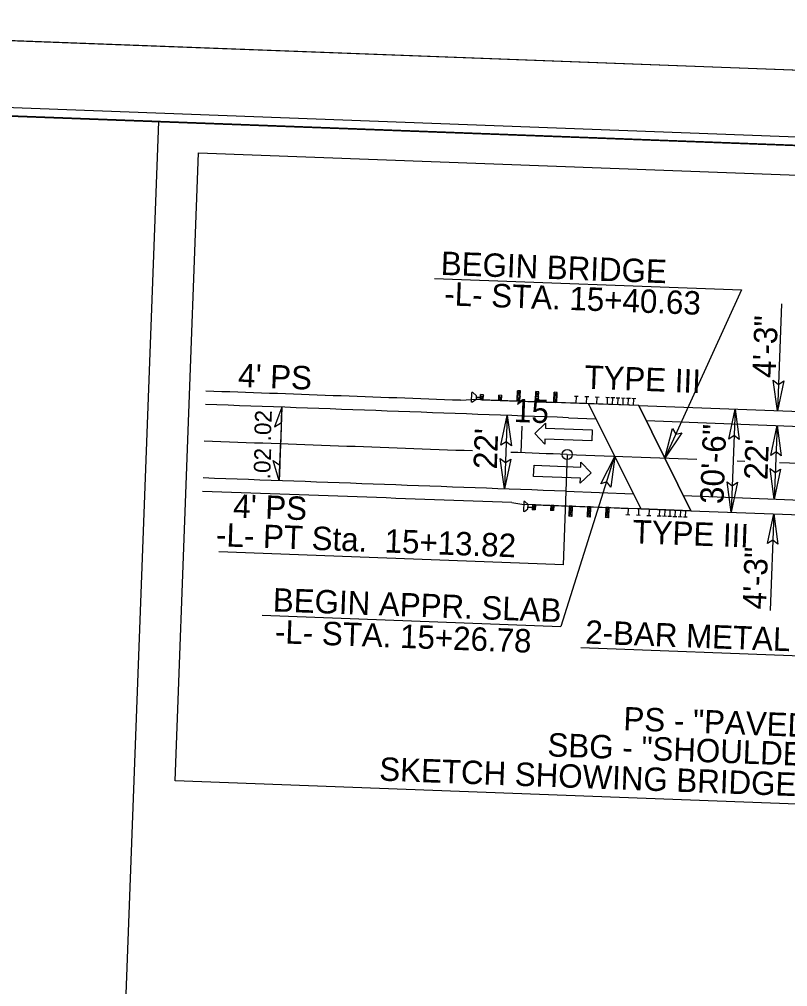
# Model space of a CAD drawing. Extents: x 2170073 to 2172001, y 723518 to 724675.
# Drawn here: x 2170287.7 to 2170517.6, y 724386.1 to 724675.4 of the extents above; entities that cross this region are included whole.
import ezdxf

# ---------------------------------------------------------------- set-up
doc = ezdxf.new("R2010")
doc.units = 0
for name, color, linetype in [('Prop Approach Slab', 7, 'Continuous'), ('Prop Approach Slab Hatching', 7, 'Continuous'), ('Prop Dimension', 7, 'Continuous'), ('Prop DSN Text', 7, 'Continuous'), ('Prop EOT', 7, 'Continuous'), ('Prop Guardrail', 7, 'Continuous'), ('Prop Guardrail Anchor Unit CELL', 7, 'Continuous'), ('Prop Horizontal Alignment', 7, 'Continuous'), ('Prop Horizontal Alignment Station Label', 7, 'Continuous'), ('Prop Horizontal Alignment Tick Label', 7, 'Continuous'), ('Prop Horizontal Alignment Tick Large', 7, 'Continuous'), ('Prop Lane Arrow CELL', 7, 'Continuous'), ('Prop Paved Shoulder', 7, 'Continuous'), ('Prop Roadway Bridge', 7, 'Continuous'), ('Prop Structure Anchor Unit CELL', 7, 'Continuous'), ('Prop Superelevation  Arrow CELL', 7, 'Continuous'), ('Prop Superelevation Label', 7, 'Continuous'), ('Prop Terminator CELL', 7, 'Continuous'), ('Sheet Clip Boundary CELL', 7, 'Continuous'), ('Sheet Cutting Line CELL', 7, 'Continuous'), ('Sheet Plan CELL', 7, 'Continuous'), ('Sheet Plan Layout CELL', 7, 'Continuous'), ('Sheet Plot Border Inside CELL', 7, 'Continuous'), ('Sheet Plot Border Outside CELL', 7, 'Continuous')]:
    doc.layers.add(name, color=color, linetype=linetype)

msp = doc.modelspace()

# ---------------------------------------------------------------- linework, layer by layer
at = {"layer": 'Prop Approach Slab'}
for p, q in [((2170473.03, 724559.86), (2170458.04, 724560.42)), ((2170458.04, 724560.42), (2170473.62, 724528.98)), ((2170488.61, 724528.42), (2170473.62, 724528.98))]:
    msp.add_line(p, q, dxfattribs=at)
at = {"layer": 'Prop Approach Slab Hatching'}
msp.add_lwpolyline([(2170473.62, 724528.98), (2170488.61, 724528.42), (2170473.03, 724559.86), (2170458.04, 724560.42)], close=True, dxfattribs=at)
at = {"layer": 'Prop Dimension'}
for p, q in [((2170411.96, 724597.89), (2170503.73, 724594.46)), ((2170503.73, 724594.46), (2170480.82, 724544.14)), ((2170515.76, 724590.29), (2170514.56, 724558.31)), ((2170433.67, 724556.91), (2170432.85, 724534.93)), ((2170501.86, 724558.78), (2170500.71, 724527.97)), ((2170514.4, 724553.89), (2170513.57, 724531.91)), ((2170465.83, 724544.7), (2170449.78, 724493.81)), ((2170513.41, 724527.5), (2170512.33, 724498.61)), ((2170360.39, 724497.16), (2170449.78, 724493.81)), ((2170455.76, 724487.5), (2170541.42, 724484.3))]:
    msp.add_line(p, q, dxfattribs=at)
at = {"layer": 'Prop DSN Text'}
msp.add_lwpolyline([(2170341.34, 724635.49), (2170729.53, 724620.96), (2170722.5, 724433.09), (2170334.32, 724447.61)], close=True, dxfattribs=at)
at = {"layer": 'Prop EOT'}
for p, q in [((2170452.07, 724556.23), (2170460.27, 724555.92)), ((2170451.25, 724534.24), (2170471.39, 724533.49))]:
    msp.add_line(p, q, dxfattribs=at)
for radius, end in [(58536.88, 87.9639731), (58514.88, 87.9639098)]:
    msp.add_arc((2168263.72, 666060.26), radius, 87.8575428, end, dxfattribs=at)
at = {"layer": 'Prop Guardrail'}
for p, q in [((2170454.29, 724560.56), (2170448.05, 724560.79)), ((2170463.63, 724529.36), (2170469.87, 724529.12))]:
    msp.add_line(p, q, dxfattribs=at)
at = {"layer": 'Prop Guardrail Anchor Unit CELL'}
for p, q in [((2170423.03, 724560.87), (2170423.15, 724563.81)), ((2170423.42, 724563.8), (2170423.15, 724563.81)), ((2170423.42, 724563.8), (2170424.41, 724562.9)), ((2170424.41, 724562.9), (2170424.37, 724561.68)), ((2170424.4, 724562.4), (2170425.69, 724562.35)), ((2170425.66, 724561.62), (2170425.72, 724563.14)), ((2170426.59, 724563.11), (2170425.66, 724561.62)), ((2170426.54, 724561.59), (2170425.71, 724563.14)), ((2170426.59, 724563.11), (2170425.72, 724563.14)), ((2170426.54, 724561.59), (2170426.59, 724563.11)), ((2170431.15, 724561.42), (2170431.2, 724562.94)), ((2170432.08, 724562.9), (2170431.15, 724561.42)), ((2170432.08, 724562.9), (2170431.2, 724562.94)), ((2170432.02, 724561.39), (2170431.2, 724562.94)), ((2170432.02, 724561.39), (2170432.08, 724562.9)), ((2170436.63, 724561.22), (2170436.75, 724564.25)), ((2170437.57, 724562.7), (2170436.63, 724561.22)), ((2170436.69, 724562.73), (2170437.62, 724564.22)), ((2170437.57, 724562.7), (2170436.69, 724562.73)), ((2170437.51, 724561.18), (2170436.69, 724562.73)), ((2170437.62, 724564.22), (2170436.75, 724564.25)), ((2170436.75, 724564.25), (2170437.57, 724562.7)), ((2170437.51, 724561.18), (2170437.62, 724564.22)), ((2170442.12, 724561.01), (2170442.23, 724564.05)), ((2170443.06, 724562.5), (2170442.12, 724561.01)), ((2170442.18, 724562.53), (2170443.11, 724564.01)), ((2170443.06, 724562.5), (2170442.18, 724562.53)), ((2170443, 724560.98), (2170442.18, 724562.53)), ((2170443.11, 724564.01), (2170442.23, 724564.05)), ((2170442.23, 724564.05), (2170443.06, 724562.5)), ((2170443, 724560.98), (2170443.11, 724564.01)), ((2170447.61, 724560.81), (2170447.72, 724563.84)), ((2170448.54, 724562.29), (2170447.61, 724560.81)), ((2170447.66, 724562.33), (2170448.6, 724563.81)), ((2170448.54, 724562.29), (2170447.66, 724562.33)), ((2170448.49, 724560.78), (2170447.66, 724562.33)), ((2170448.6, 724563.81), (2170447.72, 724563.84)), ((2170447.72, 724563.84), (2170448.54, 724562.29)), ((2170448.49, 724560.78), (2170448.6, 724563.81)), ((2170423.3, 724560.86), (2170423.03, 724560.87)), ((2170424.37, 724561.68), (2170423.3, 724560.86)), ((2170425.66, 724561.63), (2170424.37, 724561.68)), ((2170426.54, 724561.59), (2170425.66, 724561.62)), ((2170426.1, 724561.6), (2170448.05, 724560.79)), ((2170432.02, 724561.39), (2170431.15, 724561.42)), ((2170437.51, 724561.18), (2170436.63, 724561.22)), ((2170443, 724560.98), (2170442.12, 724561.01)), ((2170448.49, 724560.78), (2170447.61, 724560.81)), ((2170438.68, 724531.15), (2170438.57, 724528.21)), ((2170438.95, 724531.14), (2170438.68, 724531.15)), ((2170439.95, 724530.24), (2170438.95, 724531.14)), ((2170438.84, 724528.2), (2170438.57, 724528.21)), ((2170438.84, 724528.2), (2170439.9, 724529.02)), ((2170439.9, 724529.02), (2170439.95, 724530.24)), ((2170439.92, 724529.52), (2170441.21, 724529.48)), ((2170441.24, 724530.2), (2170439.95, 724530.24)), ((2170441.24, 724530.21), (2170441.18, 724528.69)), ((2170442.12, 724530.17), (2170441.18, 724528.69)), ((2170442.06, 724528.66), (2170441.18, 724528.69)), ((2170442.12, 724530.17), (2170441.24, 724530.21)), ((2170442.06, 724528.66), (2170441.24, 724530.21)), ((2170441.68, 724530.19), (2170463.63, 724529.36)), ((2170442.12, 724530.17), (2170442.06, 724528.66)), ((2170446.73, 724530), (2170446.67, 724528.48)), ((2170447.6, 724529.97), (2170446.67, 724528.48)), ((2170447.55, 724528.45), (2170446.67, 724528.48)), ((2170447.6, 724529.97), (2170446.73, 724530)), ((2170447.55, 724528.45), (2170446.73, 724530)), ((2170447.6, 724529.97), (2170447.55, 724528.45)), ((2170452.21, 724529.79), (2170452.1, 724526.76)), ((2170452.1, 724526.76), (2170453.03, 724528.24)), ((2170453.09, 724529.76), (2170452.15, 724528.28)), ((2170453.03, 724528.24), (2170452.15, 724528.28)), ((2170452.15, 724528.28), (2170452.98, 724526.73)), ((2170453.09, 724529.76), (2170452.21, 724529.79)), ((2170453.03, 724528.24), (2170452.21, 724529.79)), ((2170453.09, 724529.76), (2170452.98, 724526.73)), ((2170457.7, 724529.58), (2170457.59, 724526.55)), ((2170457.59, 724526.55), (2170458.52, 724528.03)), ((2170458.58, 724529.55), (2170457.64, 724528.07)), ((2170458.52, 724528.03), (2170457.64, 724528.07)), ((2170457.64, 724528.07), (2170458.46, 724526.52)), ((2170458.58, 724529.55), (2170457.7, 724529.58)), ((2170458.52, 724528.03), (2170457.7, 724529.58)), ((2170458.58, 724529.55), (2170458.46, 724526.52)), ((2170463.19, 724529.38), (2170463.07, 724526.34)), ((2170463.07, 724526.34), (2170464.01, 724527.83)), ((2170464.07, 724529.34), (2170463.13, 724527.86)), ((2170464.01, 724527.83), (2170463.13, 724527.86)), ((2170463.13, 724527.86), (2170463.95, 724526.31)), ((2170464.07, 724529.34), (2170463.19, 724529.38)), ((2170464.01, 724527.83), (2170463.19, 724529.38)), ((2170464.07, 724529.34), (2170463.95, 724526.31)), ((2170452.98, 724526.73), (2170452.1, 724526.76)), ((2170458.46, 724526.52), (2170457.59, 724526.55)), ((2170463.95, 724526.31), (2170463.07, 724526.34))]:
    msp.add_line(p, q, dxfattribs=at)
at = {"layer": 'Prop Horizontal Alignment'}
for p, q in [((2170451.66, 724545.23), (2170490.37, 724543.78)), ((2170502.53, 724543.33), (2170504.82, 724543.24)), ((2170515.16, 724542.86), (2170677.93, 724536.77))]:
    msp.add_line(p, q, dxfattribs=at)
for start, end in [(87.8852982, 87.9639415), (87.8575428, 87.8740672)]:
    msp.add_arc((2168263.72, 666060.26), 58525.88, start, end, dxfattribs=at)
at = {"layer": 'Prop Horizontal Alignment Station Label'}
for p, q in [((2170451.66, 724545.23), (2170450.43, 724512.25)), ((2170447.91, 724512.34), (2170347.45, 724516.1)), ((2170450.43, 724512.25), (2170447.91, 724512.34))]:
    msp.add_line(p, q, dxfattribs=at)
msp.add_circle((2170451.66, 724545.23), 1.5, dxfattribs=at)
at = {"layer": 'Prop Horizontal Alignment Tick Large'}
msp.add_line((2170437.85, 724545.75), (2170438.15, 724553.74), dxfattribs=at)
at = {"layer": 'Prop Lane Arrow CELL'}
for p, q in [((2170441.91, 724551.54), (2170445.17, 724554.62)), ((2170445.17, 724554.62), (2170445.12, 724553.12)), ((2170444.94, 724548.32), (2170441.91, 724551.54)), ((2170445.12, 724553.12), (2170459.11, 724552.59)), ((2170459.11, 724552.59), (2170458.98, 724549.3)), ((2170444.99, 724549.82), (2170444.94, 724548.32)), ((2170458.98, 724549.3), (2170444.99, 724549.82)), ((2170441.58, 724538.69), (2170441.71, 724541.99)), ((2170441.71, 724541.99), (2170455.7, 724541.47)), ((2170455.7, 724541.47), (2170455.75, 724542.96)), ((2170455.75, 724542.96), (2170458.78, 724539.75)), ((2170458.78, 724539.75), (2170455.52, 724536.67)), ((2170455.57, 724538.17), (2170441.58, 724538.69)), ((2170455.52, 724536.67), (2170455.57, 724538.17))]:
    msp.add_line(p, q, dxfattribs=at)
at = {"layer": 'Prop Paved Shoulder'}
for p, q in [((2170419.72, 724561.43), (2170423.07, 724561.72)), ((2170458.04, 724560.42), (2170423.07, 724561.72)), ((2170435.11, 724530.84), (2170438.64, 724530.31)), ((2170469.87, 724529.12), (2170438.64, 724530.31)), ((2170473.62, 724528.98), (2170469.87, 724529.12))]:
    msp.add_line(p, q, dxfattribs=at)
for radius, start, end in [(58540.88, 87.8893792, 87.9639847), (58510.88, 87.8732127, 87.9638983)]:
    msp.add_arc((2168263.72, 666060.26), radius, start, end, dxfattribs=at)
at = {"layer": 'Prop Roadway Bridge'}
for p, q in [((2170473.03, 724559.86), (2170597.1, 724555.22)), ((2170473.03, 724559.86), (2170488.61, 724528.42)), ((2170475.26, 724555.36), (2170599.57, 724550.71)), ((2170486.38, 724532.93), (2170611.89, 724528.23)), ((2170488.61, 724528.42), (2170614.36, 724523.72))]:
    msp.add_line(p, q, dxfattribs=at)
at = {"layer": 'Prop Structure Anchor Unit CELL'}
for p, q in [((2170454.94, 724562.54), (2170453.8, 724562.58)), ((2170454.29, 724560.56), (2170454.37, 724562.56)), ((2170458.06, 724562.42), (2170456.92, 724562.47)), ((2170457.42, 724560.45), (2170457.49, 724562.44)), ((2170461.19, 724562.31), (2170460.04, 724562.35)), ((2170460.54, 724560.33), (2170460.61, 724562.33)), ((2170464.31, 724562.19), (2170463.16, 724562.23)), ((2170463.66, 724560.21), (2170463.74, 724562.21)), ((2170465.87, 724562.13), (2170464.73, 724562.17)), ((2170465.22, 724560.15), (2170465.3, 724562.15)), ((2170473.03, 724559.86), (2170454.29, 724560.56)), ((2170467.43, 724562.07), (2170466.29, 724562.11)), ((2170466.79, 724560.09), (2170466.86, 724562.09)), ((2170468.99, 724562.01), (2170467.85, 724562.06)), ((2170468.35, 724560.04), (2170468.42, 724562.03)), ((2170470.56, 724561.96), (2170469.41, 724562)), ((2170469.91, 724559.98), (2170469.98, 724561.98)), ((2170472.12, 724561.9), (2170470.97, 724561.94)), ((2170471.47, 724559.92), (2170471.54, 724561.92)), ((2170469.87, 724529.12), (2170469.8, 724527.13)), ((2170488.61, 724528.42), (2170469.87, 724529.12)), ((2170472.99, 724529.01), (2170472.92, 724527.01)), ((2170476.12, 724528.89), (2170476.04, 724526.89)), ((2170479.24, 724528.77), (2170479.17, 724526.78)), ((2170480.8, 724528.72), (2170480.73, 724526.72)), ((2170482.36, 724528.66), (2170482.29, 724526.66)), ((2170483.92, 724528.6), (2170483.85, 724526.6)), ((2170485.49, 724528.54), (2170485.41, 724526.54)), ((2170487.05, 724528.48), (2170486.97, 724526.48)), ((2170470.37, 724527.1), (2170469.22, 724527.15)), ((2170473.49, 724526.99), (2170472.35, 724527.03)), ((2170476.62, 724526.87), (2170475.47, 724526.91)), ((2170479.74, 724526.75), (2170478.59, 724526.8)), ((2170481.3, 724526.7), (2170480.15, 724526.74)), ((2170482.86, 724526.64), (2170481.72, 724526.68)), ((2170484.42, 724526.58), (2170483.28, 724526.62)), ((2170485.98, 724526.52), (2170484.84, 724526.56)), ((2170487.54, 724526.46), (2170486.4, 724526.5))]:
    msp.add_line(p, q, dxfattribs=at)
at = {"layer": 'Prop Superelevation  Arrow CELL'}
for p, q in [((2170366.31, 724559.37), (2170365.86, 724547.38)), ((2170365.49, 724537.39), (2170365.94, 724549.38))]:
    msp.add_line(p, q, dxfattribs=at)
for points in [[(2170366.31, 724559.37), (2170364.09, 724553.45), (2170366.14, 724554.75)], [(2170365.49, 724537.39), (2170363.71, 724543.46), (2170365.66, 724542.01)]]:
    msp.add_lwpolyline(points, close=True, dxfattribs=at)
at = {"layer": 'Prop Superelevation Label'}
msp.add_line((2170366.31, 724559.37), (2170365.49, 724537.39), dxfattribs=at)
at = {"layer": 'Prop Terminator CELL'}
for points in [[(2170516.45, 724567.24), (2170514.56, 724558.31), (2170513.3, 724567.41), (2170514.86, 724566.2)], [(2170431.78, 724547.98), (2170433.67, 724556.91), (2170434.93, 724547.81), (2170433.37, 724549.02)], [(2170499.98, 724549.85), (2170501.86, 724558.78), (2170503.12, 724549.68), (2170501.57, 724550.89)], [(2170512.51, 724544.96), (2170514.4, 724553.89), (2170515.66, 724544.79), (2170514.1, 724546)], [(2170485.96, 724551.69), (2170480.82, 724544.14), (2170483.11, 724553.04), (2170484.09, 724551.33)], [(2170434.73, 724543.86), (2170432.85, 724534.93), (2170431.59, 724544.03), (2170433.14, 724542.82)], [(2170461.7, 724536.48), (2170465.9, 724544.59), (2170464.69, 724535.48), (2170463.51, 724537.06)], [(2170515.46, 724540.84), (2170513.57, 724531.91), (2170512.31, 724541.01), (2170513.87, 724539.8)], [(2170502.6, 724536.91), (2170500.71, 724527.97), (2170499.45, 724537.07), (2170501.01, 724535.86)], [(2170511.52, 724518.56), (2170513.41, 724527.5), (2170514.67, 724518.39), (2170513.11, 724519.6)]]:
    msp.add_lwpolyline(points, close=True, dxfattribs=at)
at = {"layer": 'Sheet Clip Boundary CELL'}
msp.add_lwpolyline([(2170290.07, 723595.53), (2171689.11, 723543.19), (2171720.45, 724381.12), (2171531.32, 724388.19), (2171539.23, 724599.53), (2170329.33, 724644.8)], close=True, dxfattribs=at)
at = {"layer": 'Sheet Cutting Line CELL'}
msp.add_line((2171796.16, 724612.42), (2170113.83, 724675.36), dxfattribs=at)
at = {"layer": 'Sheet Plan CELL'}
for points in [[(2171778.35, 724590.59), (2170279.36, 724646.67), (2170240.11, 723597.4), (2171739.07, 723541.32)], [(2170240.11, 723597.4), (2170279.34, 724646.64), (2171578.42, 724598.08), (2171572.82, 724448.12), (2171772.72, 724440.63), (2171739.07, 723541.32)]]:
    msp.add_lwpolyline(points, close=True, dxfattribs=at)
at = {"layer": 'Sheet Plan Layout CELL'}
msp.add_lwpolyline([(2170279.34, 724646.64), (2170240.11, 723597.4), (2171739.06, 723541.32), (2171770.41, 724379.25), (2171531.32, 724388.19), (2171539.23, 724599.53)], close=True, dxfattribs=at)
at = {"layer": 'Sheet Plot Border Inside CELL'}
msp.add_lwpolyline([(2170086.63, 723600.63), (2171751.46, 723538.36), (2171790.91, 724592.61), (2170126.08, 724654.89)], close=True, dxfattribs=at)
at = {"layer": 'Sheet Plot Border Outside CELL'}
msp.add_lwpolyline([(2170072.89, 723581.13), (2171755.22, 723518.19), (2171796.16, 724612.42), (2170113.83, 724675.36)], close=True, dxfattribs=at)

# ---------------------------------------------------------------- texts
at = {"layer": 'Prop DSN Text'}
for s, rotation, p in [('4\'-3"', 87.8574, (2170513.99, 724568.03)), ('30\'-6"', 87.8574, (2170498.38, 724530.34)), ("22'", 87.8574, (2170430.57, 724540.72)), ("22'", 87.8574, (2170511.53, 724537.52)), ('4\'-3"', 87.8574, (2170511.07, 724498.79)), ('PS - "PAVED SHOULDER"', 357.8574, (2170468.36, 724462.76)), ('SBG - "SHOULDER BERM GUTTER"', 357.8574, (2170445.64, 724454.97)), ('SKETCH SHOWING BRIDGE / ROADWAY RELATIONSHIP (NTS)', 357.8574, (2170395.32, 724447.71))]:
    msp.add_text(s, height=7, rotation=rotation, dxfattribs=at).set_placement(p)
at = {"layer": 'Prop Horizontal Alignment Station Label'}
msp.add_text('-L- PT Sta.  15+13.82', height=7, rotation=357.8574, dxfattribs=at).set_placement((2170346.5, 724517.82))
at = {"layer": 'Prop Horizontal Alignment Tick Label'}
msp.add_text('15', height=7, rotation=357.8711, dxfattribs=at).set_placement((2170435.63, 724554.96))
at = {"layer": 'Prop Structure Anchor Unit CELL'}
for s, p in [('BEGIN BRIDGE', (2170413.73, 724598.96)), ('-L- STA. 15+40.63', (2170414.78, 724589.86)), ("4' PS", (2170353.08, 724565.43)), ('TYPE III', (2170456.67, 724564.91)), ("4' PS", (2170351.62, 724526.39)), ('TYPE III', (2170471.06, 724518.7)), ('BEGIN APPR. SLAB', (2170363.49, 724498.3)), ('-L- STA. 15+26.78', (2170364.12, 724488.81)), ('2-BAR METAL RAIL', (2170456.94, 724488.68))]:
    msp.add_text(s, height=7, rotation=357.8574, dxfattribs=at).set_placement(p)
at = {"layer": 'Prop Superelevation Label'}
for p in [(2170362.96, 724549.11), (2170362.76, 724537.76)]:
    msp.add_text('.02', height=5, rotation=87.8574, dxfattribs=at).set_placement(p)

doc.saveas('drawing.dxf')
